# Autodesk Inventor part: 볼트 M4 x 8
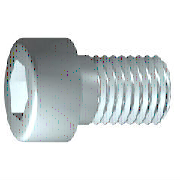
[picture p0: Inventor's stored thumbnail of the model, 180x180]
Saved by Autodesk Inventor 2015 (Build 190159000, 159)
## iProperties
IsCustomPart: 1
Created: 2012-02
Part Number: 볼트 M4 x 8
Material: 스테인리스강
Description: 6각 소켓 머리 캡 나사
Document SubType Name: Modeling
Standard: ISO 4762
Designer: mduedu
Standard Revision: Fourth edition 2004-03-01
Standards Organization: ISO
Language: ko-KR
Size Designation: M4 x 8
Categories: <MemberInstance><Categories><Category DisplayName="조임쇠" InternalName="e4da775c-781d-43d5-af7c-5136215cf5a6" Mnemonic="FSTN"><Category DisplayName="볼트" InternalN
Density: 8.08 g/cm^3
Appearance: 반광택
Mass: 1.89105 g
Surface Area: 2.80587 cm^2
Volume: 0.234041 cm^3
Author: mduedu
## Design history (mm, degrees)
sketch "스케치1"
  geometry: L1 (-1, 0)-(8, 0); L2 (8, 0)-(8, 2); L3 (8, 2)-(1.75, 2); L4 (1.75, 2)-(1.32, 2); L5 (1.32, 2)-(0, 2); L6 (0, 2)-(0, 3.5); L7 (0, 3.5)-(-4, 3.5); L8 (-4, 3.5)-(-4, 1.732); L9 (-4, 1.732)-(-2, 1.732); L10 (-2, 1.732)-(-1, 0); L11 (-6.4, 0)-(10.4, 0) reference; L12 (0, -0.7)-(0, 4.2) reference; L13 (1.75, 2)-(0, 2)
  constraints: 22 end point, 6 parallel, 2 collinear, 2 perpendicular, 1 horizontal, 1 point on line
  dimensions: "d1" = 6.25 distance from line of L3.end L2 (= GEL); "d2" = 0.42952 distance of L4.end L3.end (computed from GAL); "d3" = 4 distance between parallel lines of L8 L6 (= KOH); "d4" = 2 distance of L8.end L9.end (= INTI); "d5" = 60 deg angle of L10 L1; "d6" = 4 diameter of L3 L1 (= GD); "d7" = 4 diameter of L5 L1 (= BDM); "d8" = 3.4641 diameter of L9 L1 (= 1.1547 x SW); "d9" = 7 diameter of L7 L1 (= KOD); "d26" = 8 distance between parallel lines of L12 L2 (= NLG)
revolve "본체" sketch "스케치1" stored, may be unused: angle "d10" = 90 deg
sketch "스케치2"
  geometry: L1 (0, -4.9)-(0, 4.9) reference; L2 (-4.9, 0)-(4.9, 0) reference; L3 (1.732, 0)-(0.866, -1.5); L4 (0.866, -1.5)-(-0.866, -1.5); L5 (-0.866, -1.5)-(-1.732, 0); L6 (-1.732, 0)-(-0.866, 1.5); L7 (-0.866, 1.5)-(0.866, 1.5); L8 (0.866, 1.5)-(1.732, 0); 2 further points
  constraints: 12 end point, 1 coincident, 1 horizontal alignment, 1 point on line, 12 other
extrude "슬롯" join sketch "스케치2" stored distance "d11" = 10; taper "d12" = 0 deg
workplane "Work Plane1"
fillet "Fillet2" dims "d30" = 0.1 (= R)
body "Solid1"
fillet "모깎기1" dims "d17" = 0.4 (= RR)
feature "스레드" dims "d13" = 6.25 (= GEL), "d14" = 0
chamfer "모따기1" distance "d15" = 0.42941 (= -0.5 x SPD + 0.5 x GD); stored, may be unused: second distance "d16" = 0.42941 (= GUL), angle "d27" = 45 deg
other parameters: "GD" = 4 [user parameter; used in 2 equation terms], "NLG" = 8 [user parameter; used in 1 equation term], "GEL" = 6.25 [user parameter; used in 2 equation terms], "KOD" = 7 [user parameter; used in 1 equation term], "KOH" = 4 [user parameter; used in 1 equation term], "INTI" = 2 [user parameter; used in 1 equation term], "GAL" = 0.42941 (= 0.61345 x PTC) [user parameter; used in 1 equation term], "GUL" = 0.42941 (= 0.61345 x PTC) [user parameter; used in 1 equation term], "BDM" = 4 (= NND) [user parameter; used in 1 equation term], "SW" = 3 [user parameter; used in 2 equation terms], "RR" = 0.4 [user parameter; used in 1 equation term], "SPD" = 3.14117 (= NND - 1.2269 x PTC) [user parameter; used in 1 equation term], "d19" = 0, "d28" = 0, "d29" = 0, "R" = 0.1 [user parameter; used in 1 equation term], "TOA" = 30 deg [user parameter], "GD1" = 3.14117 (= THREADDIA - 1.2269 x PTC) [user parameter], "THREADDIA" = 4 [user parameter; used in 1 equation term], "FAWI" = 45 deg [user parameter], "TPU" = 14.28571 (computed from PTC) [user parameter], "PTC" = 0.7 [user parameter; used in 5 equation terms], "NND" = 4 [user parameter; used in 2 equation terms], "E0" = 3.465 (= 1.155 x SW) [user parameter]
